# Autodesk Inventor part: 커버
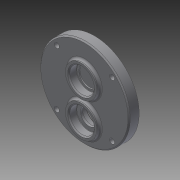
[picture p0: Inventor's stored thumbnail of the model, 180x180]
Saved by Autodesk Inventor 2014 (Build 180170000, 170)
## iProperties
Created: 2015-07
Part Number: 커버
Material: Generic
Document SubType Name: Modeling
Designer: Administrator
Density: 1 g/cm^3
Appearance: Default
Author: Administrator
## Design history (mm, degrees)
sketch "스케치1"
  geometry: C1 r 40 at (0, 0); 1 further point
  constraints: 1 centre point, 1 coincident
  dimensions: "d0" = 80 diameter of C1
extrude "돌출1" new body sketch "스케치1" distance "d1" = 9; taper "d2" = 0 deg
sketch "스케치2"
  geometry: C1 r 40 at (0, 0) reference; C2 r 14 at (0, 11); C3 r 14 at (0, -20)
  constraints: 2 centre point, 2 vertical alignment
  dimensions: "d3" = 28 diameter of C2; "d4" = 28 diameter of C3; "d5" = 11 distance of C1.centre C2.centre; "d6" = 20 distance of C3.centre C1.centre
extrude "돌출2" join sketch "스케치2" distance "d7" = 3; taper "d8" = 0 deg
sketch "스케치3"
  geometry: C1 r 14 at (0, 0) reference; C2 r 11 at (0, 0); 1 further point
  constraints: 1 centre point, 1 coincident
  dimensions: "d9" = 22 diameter of C2
extrude "돌출3" cut sketch "스케치3" distance "d10" = 7; taper "d11" = 0 deg
sketch "스케치4"
  geometry: C1 r 9 at (0, 0); 2 further points
  constraints: 1 centre point, 1 coincident, 1 vertical alignment
  dimensions: "d12" = 18 diameter of C1
extrude "돌출4" cut sketch "스케치4" distance "d13" = 1; taper "d14" = 0 deg
sketch "스케치5"
  geometry: C1 r 14 at (0, 0) reference; C2 r 11 at (0, 0); 1 further point
  constraints: 1 centre point, 1 coincident
  dimensions: "d15" = 22 diameter of C2
extrude "돌출5" cut sketch "스케치5" distance "d16" = 7; taper "d17" = 0 deg
sketch "스케치6"
  geometry: C1 r 11 at (0, 0) reference; C2 r 7.5 at (0, 0); 1 further point
  constraints: 1 centre point, 1 coincident
  dimensions: "d18" = 15 diameter of C2
extrude "돌출6" cut sketch "스케치6" distance "d19" = 2; taper "d20" = 0 deg
sketch "스케치9"
  geometry: C1 r 14 at (0, 20) reference; C2 r 15 at (0, 20)
  constraints: 1 centre point, 1 coincident
  dimensions: "d25" = 30 diameter of C2
extrude "돌출8" join sketch "스케치9" distance "d26" = 4; taper "d27" = 0 deg
sketch "스케치10"
  geometry: C1 r 15 at (0, 0) reference; C2 r 11 at (0, 0); 1 further point
  constraints: 1 centre point, 1 coincident
  dimensions: "d28" = 22 diameter of C2
extrude "돌출9" cut sketch "스케치10" distance "d29" = 7; taper "d30" = 0 deg
sketch "스케치11"
  geometry: L1 (0, 0)-(0, -35); L2 (24.749, -24.749)-(-24.749, 24.749); L3 (24.749, 24.749)-(-24.749, -24.749); C1 r 40 at (0, 0) reference; C2 r 4 at (-24.749, -24.749); C3 r 4 at (-24.749, 24.749); C4 r 4 at (24.749, 24.749); C5 r 4 at (24.749, -24.749); A1 r 35 centre (0, 0) between (0, -35) and (24.749, -24.749)
  constraints: 6 end point, 5 centre point, 5 coincident, 5 point on circle, 2 midpoint, 1 vertical
  dimensions: "d31" = 70 diameter of A1; "d32" = 45 deg angle of L2 L1; "d33" = 45 deg angle of L1 L3; "d34" = 8 diameter of C2; "d35" = 8 diameter of C3; "d36" = 8 diameter of C4; "d37" = 8 diameter of C5
extrude "돌출10" cut sketch "스케치11" distance "d38" = 4.4; taper "d39" = 0 deg
sketch "스케치12"
  geometry: C1 r 4 at (0, 0) reference; C2 r 4 at (0, 49.497) reference; C3 r 4 at (49.497, 49.497) reference; C4 r 4 at (49.497, 0) reference; C5 r 2.25 at (0, 49.497); C6 r 2.25 at (0, 0); C7 r 2.25 at (49.497, 0); C8 r 2.25 at (49.497, 49.497); 1 further point
  constraints: 4 centre point, 4 coincident
  dimensions: "d40" = 4.5 diameter of C5; "d41" = 4.5 diameter of C6; "d42" = 4.5 diameter of C7; "d43" = 4.5 diameter of C8
extrude "돌출11" cut sketch "스케치12" stored distance "d44" = 4.4; taper "d45" = 0 deg
chamfer "모따기1" distance "d46" = 1; stored, may be unused: second distance "d47" = 2, angle "d48" = 45 deg
fillet "모깎기1" dims "d49" = 0.3
chamfer "모따기2" distance "d50" = 1; stored, may be unused: second distance "d51" = 2, angle "d52" = 45 deg
fillet "모깎기2" dims "d53" = 2
node "솔리드1"
node "투영된 루프1"
node "투영된 루프2"
node "투영된 루프3"
